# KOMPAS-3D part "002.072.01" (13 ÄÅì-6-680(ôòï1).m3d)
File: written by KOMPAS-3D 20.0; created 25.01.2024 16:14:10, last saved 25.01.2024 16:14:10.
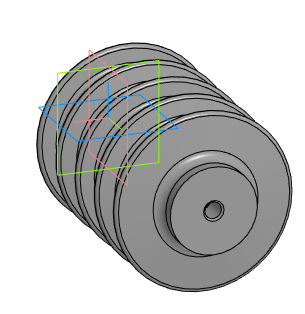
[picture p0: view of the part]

Document properties: Полное имя файла: C:\Users\drmla\OneDrive\Рабочий стол\ОПН\Модели\002.072.01.m3d

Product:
- Part/product: 002.072.01

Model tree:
1. Операция без истории:1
